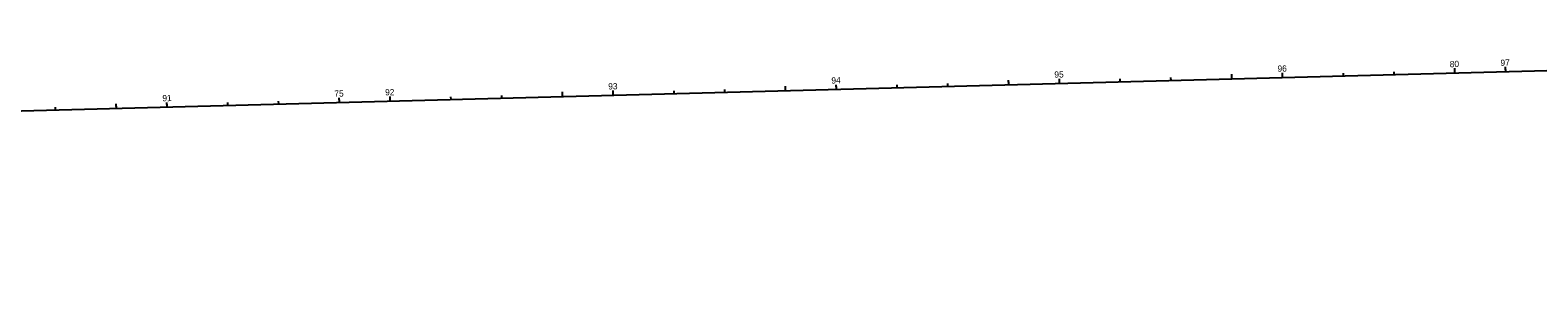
# Model space of a CAD drawing. Extents: x 2402033 to 2407434, y 498266 to 500417.
# Drawn here: x 2406072 to 2406748, y 498666 to 498783 of the extents above; entities that cross this region are included whole.
import ezdxf

# ---------------------------------------------------------------- set-up
doc = ezdxf.new("R2010")
doc.units = 0
for name, color, linetype in [('PV_P_EOP', 7, 'Continuous'), ('PV_P_Shoulder', 7, 'Continuous'), ('RD_P_GR_Lt', 7, 'Continuous'), ('SN_X_Public', 7, 'Continuous')]:
    doc.layers.add(name, color=color, linetype=linetype)

msp = doc.modelspace()

# ---------------------------------------------------------------- linework, layer by layer
at = {"layer": 'PV_P_EOP'}
msp.add_line((2403004.47, 498665.82), (2407431.7, 498783.04), dxfattribs=at)
at = {"layer": 'PV_P_Shoulder'}
for p, q in [((2406710.42, 498763.94), (2406710.37, 498765.94)), ((2406733.17, 498764.54), (2406733.13, 498765.74)), ((2406510.49, 498758.65), (2406510.46, 498759.84)), ((2406533.24, 498759.25), (2406533.18, 498761.25)), ((2406610.46, 498761.29), (2406610.42, 498762.49)), ((2406633.2, 498761.89), (2406633.17, 498763.09)), ((2406210.6, 498750.71), (2406210.54, 498752.7)), ((2406233.34, 498751.31), (2406233.31, 498752.51)), ((2406310.56, 498753.35), (2406310.53, 498754.55)), ((2406333.31, 498753.95), (2406333.27, 498755.15)), ((2406410.53, 498756), (2406410.49, 498757.2)), ((2406433.27, 498756.6), (2406433.24, 498757.8)), ((2406110.63, 498748.06), (2406110.6, 498749.26)), ((2406133.38, 498748.66), (2406133.34, 498749.86))]:
    msp.add_line(p, q, dxfattribs=at)
at = {"layer": 'RD_P_GR_Lt'}
for p, q in [((2406710.42, 498763.94), (2406710.37, 498765.94)), ((2406733.17, 498764.54), (2406733.11, 498766.54)), ((2406433.27, 498756.6), (2406433.22, 498758.6)), ((2406460.51, 498757.32), (2406460.48, 498758.52)), ((2406483.25, 498757.92), (2406483.22, 498759.12)), ((2406510.49, 498758.65), (2406510.44, 498760.64)), ((2406533.24, 498759.25), (2406533.18, 498761.25)), ((2406560.47, 498759.97), (2406560.44, 498761.17)), ((2406583.22, 498760.57), (2406583.19, 498761.77)), ((2406610.46, 498761.29), (2406610.4, 498763.29)), ((2406633.2, 498761.89), (2406633.15, 498763.89)), ((2406660.44, 498762.62), (2406660.41, 498763.81)), ((2406683.18, 498763.22), (2406683.15, 498764.42)), ((2406210.6, 498750.71), (2406210.54, 498752.7)), ((2406233.34, 498751.31), (2406233.29, 498753.31)), ((2406260.58, 498752.03), (2406260.55, 498753.23)), ((2406283.32, 498752.63), (2406283.29, 498753.83)), ((2406310.56, 498753.35), (2406310.51, 498755.35)), ((2406333.31, 498753.95), (2406333.25, 498755.95)), ((2406360.54, 498754.68), (2406360.51, 498755.87)), ((2406383.29, 498755.28), (2406383.26, 498756.48)), ((2406410.53, 498756), (2406410.47, 498758)), ((2406083.39, 498747.34), (2406083.36, 498748.54)), ((2406110.63, 498748.06), (2406110.58, 498750.06)), ((2406133.38, 498748.66), (2406133.32, 498750.66)), ((2406160.61, 498749.38), (2406160.58, 498750.58)), ((2406183.36, 498749.98), (2406183.33, 498751.18))]:
    msp.add_line(p, q, dxfattribs=at)
at = {"layer": 'SN_X_Public'}
for p, q in [((2406710.42, 498763.94), (2406710.37, 498765.94)), ((2406533.24, 498759.25), (2406533.2, 498760.45)), ((2406210.6, 498750.71), (2406210.56, 498751.9))]:
    msp.add_line(p, q, dxfattribs=at)

# ---------------------------------------------------------------- texts
at = {"layer": 'PV_P_Shoulder'}
for s, p in [('80', (2406708.13, 498766.42)), ('95', (2406530.96, 498761.74)), ('75', (2406208.34, 498753.19))]:
    msp.add_text(s, height=2.8, rotation=1.5166, dxfattribs=at).set_placement(p)
at = {"layer": 'RD_P_GR_Lt'}
for s, p in [('96', (2406630.94, 498764.38)), ('97', (2406730.85, 498767.03)), ('93', (2406331.06, 498756.44)), ('94', (2406431.05, 498759.09)), ('95', (2406530.96, 498761.74)), ('91', (2406131.29, 498751.15)), ('92', (2406231.09, 498753.8))]:
    msp.add_text(s, height=2.8, rotation=1.5166, dxfattribs=at).set_placement(p)
at = {"layer": 'SN_X_Public'}
msp.add_text('80', height=2.8, rotation=1.5166, dxfattribs=at).set_placement((2406708.13, 498766.42))

doc.saveas('drawing.dxf')
